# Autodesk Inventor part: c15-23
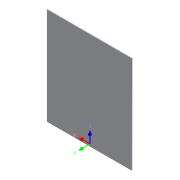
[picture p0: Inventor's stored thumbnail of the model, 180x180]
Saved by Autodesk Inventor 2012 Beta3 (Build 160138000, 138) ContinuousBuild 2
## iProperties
Created: 2011-02
Part Number: c15-23
Material: Default
Document SubType Name: Modeling
Designer: Beta-8540w
Density: 1 g/cm^3
Author: Beta-8540w
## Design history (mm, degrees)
sketch "Sketch1"
  geometry: L1 (-176.8, 203.2)-(176.8, 203.2); L2 (176.8, 203.2)-(176.8, -203.2); L3 (176.8, -203.2)-(-176.8, -203.2); L4 (-176.8, -203.2)-(-176.8, 203.2); 3 further points
  constraints: 8 end point, 2 midpoint, 2 parallel, 1 horizontal, 1 horizontal alignment, 1 perpendicular, 1 vertical alignment
  dimensions: "d0" = 353.6 distance of L2.end L3.end (computed from back_width); "d1" = 406.4 distance of L1.end L2.end (= drawer_depth)
extrude "Extrusion1" new body sketch "Sketch1" distance "d2" = 3.302 (= bottom_thickness); taper "d3" = 0 deg
body "Solid1"
other parameters: "d4" = 0, "d5" = 0, "d6" = 6.35, "d7" = 0, "d8" = 0, "d9" = 0, "back_width" = 340.9, "bottom_thickness" = 3.302, "drawer_depth" = 406.4
